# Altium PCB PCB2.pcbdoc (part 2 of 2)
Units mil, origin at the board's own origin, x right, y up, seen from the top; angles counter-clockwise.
Board outline 4920 x 2460 mil, 2 copper layers (Top Layer, Bottom Layer); 93 components, 68 nets, 331 pads, 95 vias.
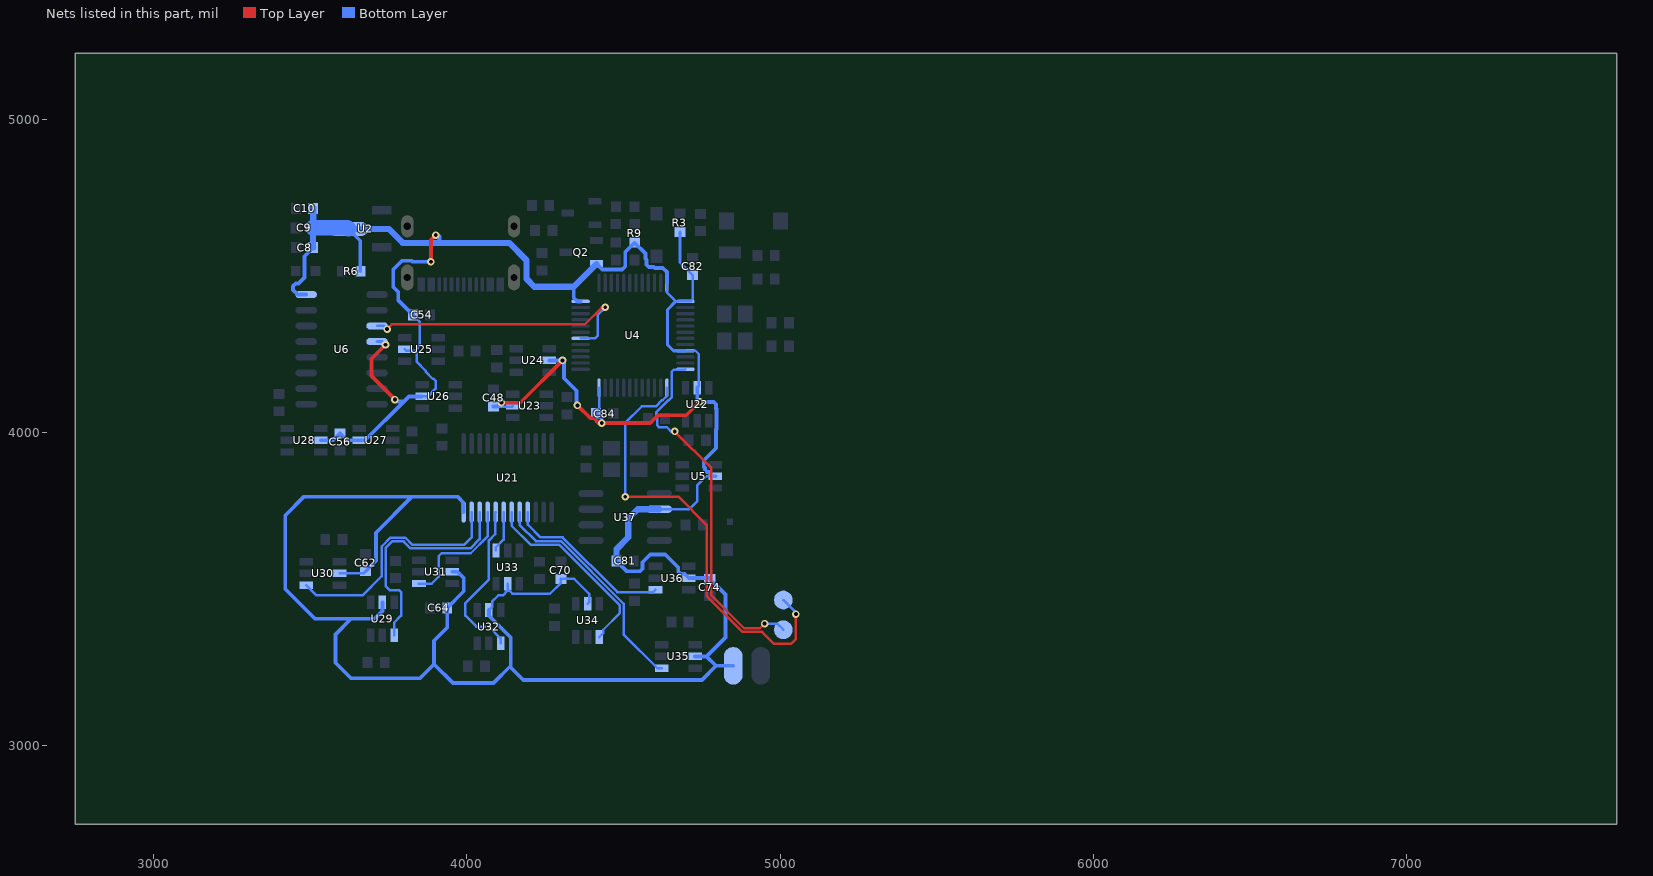
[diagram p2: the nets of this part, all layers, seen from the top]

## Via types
v1: diameter 24.02, hole 12.01, Top Layer to Bottom Layer, 95 vias

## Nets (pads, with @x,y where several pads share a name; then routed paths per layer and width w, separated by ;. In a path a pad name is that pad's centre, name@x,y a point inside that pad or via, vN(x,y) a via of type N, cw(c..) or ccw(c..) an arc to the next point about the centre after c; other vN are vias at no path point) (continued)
T9: U21.23 U30.1 | length 772.7
  Bottom Layer w8: U30.1@3486.85,3512.6 3519.45,3480 3666.87,3480 3727.98,3541.12 3727.98,3636.08 3755.91,3664.01 3802.98,3664.01 3824.98,3642.02 3992.02,3642.02 4015,3665 4015,3745.39 U21.23@4014.84,3745.55
T10: U21.22 U29.1 | length 743.4
  Bottom Layer w8: U29.1@3767.4,3351.85 3767.4,3392.4 3790,3415 3790,3490 3784.34,3495.66 3754.34,3495.66 3740,3510 3740,3631.1 3760.89,3651.99 3798.01,3651.99 3820,3630 4011.01,3630 4040.43,3659.42 U21.22@4040.43,3745.55
T11: U21.21 U31.1 | length 397.1
  Bottom Layer w8: U31.1@3846.85,3517.6 3887.6,3517.6 3910,3540 3910,3605 3919.2,3614.2 4012.2,3614.2 4066.02,3668.01 U21.21@4066.02,3745.55
T12: U21.20 U32.1 | length 528.7
  Bottom Layer w8: U21.20@4091.61,3745.55 4090,3743.94 4090,3675 4070,3655 4070,3530 3995,3455 3995,3415 4030,3380 4070,3380 4107.4,3342.6 U32.1@4107.4,3326.85
T13: U21.19 U33.1 | length 132.6
  Bottom Layer w8: U33.1@4092.6,3623.15 4092.6,3633.33 4117.2,3657.93 U21.19@4117.2,3745.55
T14: U21.18 U34.1 | length 622.2
  Bottom Layer w8: U21.18@4142.8,3745.55 4142.8,3702.2 4204.03,3640.97 4295.05,3640.97 4487.98,3448.03 4487.98,3422.98 4435,3370 4435,3359.45 U34.1@4422.4,3346.85
T15: U21.17 U35.1 | length 740.9
  Bottom Layer w8: U21.17@4168.39,3745.55 4168.39,3705 4220.41,3652.98 4300.02,3652.98 4500,3453.01 4500,3355 4607.4,3247.6 U35.1@4621.85,3247.6
T16: U21.16 U36.1 | length 540
  Bottom Layer w8: U21.16@4193.98,3745.55 4193.98,3706.02 4235,3665 4305,3665 4480,3490 4594.25,3490 U36.1@4601.85,3497.6
TX: U4.30 U6.3 | length 920.5
  Top Layer w8: v1(3745,4330) 3760,4345 4376.1,4345 4430.43,4399.33 v1(4441.75,4399.33)
  Bottom Layer w8: U6.3@3713.09,4340 3735,4340 v1(3745,4330) ; U4.30@4362.68,4300.16 4408.86,4300.16 4416.86,4308.16 4416.86,4374.43 v1(4441.75,4399.33)
USART2-RX: pad.1@5010,3465 U4.13 | length 1450.7
  Top Layer w8: v1(4505,3795) 4675,3795 4765,3705 4765,3478.01 4880.02,3362.98 4942.02,3362.98 4980,3325 5035,3325 5050,3340 v1(5050,3420)
  Bottom Layer w8: v1(4505,3795) 4505,4030 4557.98,4082.98 4602.98,4082.98 4623.17,4103.17 4624.92,4103.17 4638.27,4116.52 U4.13@4638.27,4142.68 ; pad.1@5010,3465 5050,3425 v1(5050,3420)
USART2-TX: pad.1@5010,3370 U4.12 | length 1164.8
  Top Layer w8: v1(4663.16,4003.16) 4780,3886.31 4780,3480 4885,3375 4935,3375 v1(4950,3390)
  Bottom Layer w8: v1(4663.16,4003.16) 4661.5,4001.5 4653.5,4001.5 4637.7,4017.3 4612.68,4017.3 4606.83,4023.15 4606.83,4048.17 4605,4050 4605,4065 4643.17,4103.17 4644.61,4103.17 4654.34,4112.9 4654.34,4194.34 4660,4200 4695.59,4200 U4.12@4697.32,4201.73 ; v1(4950,3390) 4990,3390 pad.1@5010,3370
VCC: C8.2 C9.2 C10.2 C48.1 C54.1 C56.1 C62.1 C64.1 C70.1 C74.1 C81.2 C82.2 C84.2 pad.1@4850,3255 Q2.2 R3.2 R6.1 R9.2 U2.2 U4.1 U4.9 U4.24 U4.36 U4.48 U5.5 U6.4 U6.16 U21.24 U22.5 U23.5 U24.5 U25.5 U26.5 U27.5 U28.5 U29.5 U30.5 U31.5 U32.5 U33.5 U34.5 U35.5 U36.5 U37.6 | length 11177.9
  Top Layer w12: v1(3740,4280) 3695,4235 3695,4180 v1(3770,4105) ; v1(3885,4545) 3885,4615 v1(3900,4630) ; v1(4110,4095) 4170,4095 v1(4305,4230) ; v1(4352.7,4086.35) 4394.05,4045 4405,4045 4420,4030 v1(4430,4030) 4585,4030 4610,4055 4700,4055 v1(4742.5,4097.5)
  Bottom Layer w8: U30.5@3593.15,3550 3669.76,3550 C62.1@3676.62,3556.86 ; U25.5@3801.85,4265 3806.19,4260.66 3834.34,4260.66 ; C54.1@3827.44,4375 3850,4352.44 3850,4281.99 3842.98,4274.98 3842.98,4269.3 3834.34,4260.66 ; U26.5@3856.85,4115 3875,4115 3900,4140 3900,4164.94 3893.95,4170.99 3890.91,4170.99 3867.97,4193.94 3867.97,4196.98 3840,4224.94 3840,4255 3834.34,4260.66 ; U32.5@4070,3433.15 4080,3443.15 4080,3460 4100,3480 4115,3480 4130,3495 U33.5@4130,3500 ; C48.1@4097.44,4082.44 4144.29,4082.44 U23.5@4146.85,4085 ; U33.5@4130,3516.85 U33.5@4130,3500 ; U34.5@4385,3453.15 4390,3458.15 4390,3485 4342.56,3532.44 C70.1@4300,3532.44 4300,3520 4265,3485 4145,3485 U33.5@4130,3500 ; C84.2@4412.44,4060 4421.73,4069.29 U4.24@4421.73,4142.68 ; U37.6@4614.15,3755 4710,3755 4735,3780 4735,3830 4765,3860 U5.5@4786.01,3860 ; U4.48@4638.27,4477.32 4638.27,4446.73 4666.73,4418.27 U4.1@4697.32,4418.27 4713.27,4418.27 4720,4425 C82.2@4720,4502.44 ; U4.9@4697.32,4260.79 4729.21,4260.79 4740,4250 4740,4148.15 U22.5@4735,4143.15
  Bottom Layer w10: U6.4@3713.09,4290 3730,4290 v1(3740,4280) ; 4666.73,4418.27 4640,4391.54 4640,4280 4659.21,4260.79 U4.9@4697.32,4260.79 ; R3.2@4680,4640.34 4680,4542.44 C82.2@4720,4502.44
  Bottom Layer w12: U6.16@3486.91,4440 3460,4440 3445,4455 3445,4467 3453.49,4475.49 3462.32,4475.49 3481.26,4494.42 3481.26,4562.36 C8.2@3509.11,4590.21 ; U28.5@3533.15,3975 3572.44,3975 C56.1@3595,3997.56 3617.56,3975 U27.5@3656.85,3975 3675,3975 3799.01,4099.01 ; U2.2@3621.61,4649.66 3659.66,4611.61 R6.1@3659.66,4515 ; C62.1@3676.62,3556.86 3710,3590.24 3710,3680 3825,3795 ; U29.5@3730,3458.15 3730,3430 3705,3405 3630,3405 ; v1(3770,4105) 3775.99,4099.01 3799.01,4099.01 ; C54.1@3827.44,4375 3781.01,4421.43 3781.01,4447.76 3765,4463.77 3765,4520 3792.95,4547.95 3823.04,4547.95 3825.99,4545 v1(3885,4545) ; U26.5@3856.85,4115 3815,4115 3799.01,4099.01 ; v1(3900,4630) 3907.89,4630 3913.47,4624.42 3913.47,4616.53 3901.94,4605 ; U31.5@3953.15,3555 3970,3555 3990,3535 3990,3492.84 C64.1@3936.95,3439.79 3936.95,3376.95 3895,3335 3895,3260 ; U21.24@3989.25,3745.55 3989.25,3775.75 3970,3795 3825,3795 ; U32.5@4070,3433.15 4070,3415 4140,3345 4140,3255 ; C48.1@4085,4082.44 4097.44,4082.44 v1(4110,4095) ; U24.5@4263.15,4230 v1(4305,4230) 4310,4225 4310,4172.97 4349.7,4133.27 4349.7,4089.35 v1(4352.7,4086.35) ; 4340.75,4465 4340.75,4430 4352.48,4418.27 U4.36@4362.68,4418.27 ; C84.2@4412.44,4060 4430,4042.44 v1(4430,4030) ; Q2.2@4413.74,4537.99 4431.74,4520 4494.9,4520 4505,4530.1 4505,4575.61 R9.2@4535.12,4605.73 4570,4570.85 4570,4555 4573.45,4551.55 4573.45,4535.47 4580.47,4528.45 4596.55,4528.45 4600,4525 4625,4525 4638.27,4511.73 U4.48@4638.27,4477.32 ; C81.2@4477.44,3590 4510.93,3556.51 4551.51,3556.51 4560,3565 4560,3567.03 4560.29,3567.32 4560.29,3585.29 4585,3610 4633.15,3610 4674.51,3568.64 4674.51,3555.62 4681.53,3548.6 4694.55,3548.6 U36.5@4708.15,3535 4772.56,3535 C74.1@4775,3532.56 4825,3482.56 4825,3345 4765,3285 ; U35.5@4728.15,3285 4765,3285 ; U22.5@4735,4143.15 4735,4105 v1(4742.5,4097.5) 4787.5,4097.5 4795,4090 4795,4076.33 4796.39,4074.94 4796.39,4010.43 4795,4009.04 4795,3949.66 4756.01,3910.67 4756.01,3890 4759.51,3886.5 4759.51,3880.62 4766.53,3873.6 4772.4,3873.6 4786.01,3860 U5.5@4793.15,3860 ; pad.1@4850,3255 4795,3255 ; 3630,3405 3580,3355 3580,3265 3630,3215 3850,3215 3895,3260 ; 3630,3405 3515,3405 3420,3500 3420,3735 3480,3795 3825,3795 ; 3895,3260 3955,3200 4085,3200 4140,3255 ; 4140,3255 4140,3250 4180,3210 4750,3210 4795,3255 ; 4765,3285 4795,3255
  Bottom Layer w20: C8.2@3509.11,4590.21 3508.17,4591.15 C9.2@3508.17,4653.08 3509.11,4654.02 C10.2@3509.11,4715.21 ; U2.2@3621.61,4649.66 3750.34,4649.66 3795,4605 3901.94,4605 4135,4605 4190,4550 4190,4490 4215,4465 4340.75,4465 Q2.2@4413.74,4537.99 ; C81.2@4477.44,3590 4477.44,3627.44 4515,3665 4515,3725 4545,3755 U37.6@4614.15,3755
  Bottom Layer w50: C9.2@3508.17,4653.08 3618.19,4653.08 U2.2@3621.61,4649.66
pads on no net: C4.1 C5.1 C6.1 C8.1 C9.1 C10.1 C12.1 C45.1 C47.1 C48.2 C49.1 C51.1 C53.1 C54.2 C55.1 C56.2 C57.1 C59.1 C61.1 C62.2 C63.1 C64.2 C65.1 C67.1 C69.1 C70.2 C71.1 C73.1 C74.2 C75.2 C76.1 C77.2 C78.2 C79.2 C80.2 C81.1 C82.1 C84.1 C85.1 SW5.1 U2.1 U4.2 U4.8 U4.10 U4.11 U4.16 U4.18 U4.19 U4.20 U4.21 U4.22 U4.23 U4.25 U4.26 U4.27 U4.28 U4.29 U4.34 U4.35 U4.37 U4.38 U4.45 U4.46 U4.47 U5.2 U5.4 U5.6 U6.1@3713.09,4440 U6.2@4830,3625 U6.7 U6.8 U6.9 U6.10 U6.11 U6.12 U6.15 U21.12 U21.15 U22.2 U22.4 U22.6 U23.2 U23.4 U23.6 U24.2 U24.4 U24.6 U25.2 U25.4 U25.6 U26.2 U26.4 U26.6 U27.2 U27.4 U27.6 U28.2 U28.4 U28.6 U29.2 U29.4 U29.6 U30.2 U30.4 U30.6 U31.2 U31.4 U31.6 U32.2 U32.4 U32.6 U33.2 U33.4 U33.6 U34.2 U34.4 U34.6 U35.2 U35.4 U35.6 U36.2 U36.4 U36.6 U37.8 U38.2 U38.4 U39.1 USB1.1 USB1.2 USB1.3 USB1.4 USB1.A1B12 USB1.A5 USB1.A8 USB1.B1A12 USB1.B5 USB1.B8 X1.2 X1.4
copper on no net: | length 4996.4
  Top Layer w8: v1(3695,4425) 3680,4440 3680,4615 3723.01,4658.01 3809.92,4658.01
  Bottom Layer w8: 3453.53,4515.14 3453.99,4515.6 3453.99,4590.21 ; 3486.85,3550 3515,3550 3530,3565 3530,3585.08 3602.58,3657.66 3630.93,3657.66 3676.62,3611.98 ; v1(3695,4425) 3698.09,4425 3713.09,4440 ; 3728.39,4709.06 3758.88,4709.06 3809.92,4658.01 ; 3763.15,3975 3797.44,3975 3825,4002.56 3865.42,4002.56 3893.17,3974.81 3902.63,3974.81 3920,3957.44 ; 3882.56,4375 3933.36,4324.2 3933.94,4324.2 3939.79,4318.35 3939.79,4317.77 3945,4312.56 3945,4300 3939.79,4294.79 3939.79,4286.45 3933.94,4280.6 3925.6,4280.6 3910,4265 3908.15,4265 ; 4057.58,3253.74 4070,3266.15 4070,3326.85 ; 4085,4137.56 4095,4147.56 4095,4207.44 4117.56,4230 4156.85,4230 4160,4230 4175.6,4214.4 4182.64,4214.4 4188.49,4208.55 4188.49,4201.51 4230,4160 4272.56,4160 4320,4112.56 4292.44,4085 4253.15,4085 ; 4150.08,4658.01 4150.08,4615.4 4208.02,4557.46 4208.02,4549.42 4240,4517.44 ; 4219.57,3745.55 4219.57,3725.43 4228.01,3716.99 4228.01,3711.95 4238.06,3701.9 4243.1,3701.9 4255,3690 4280,3690 4292.98,3702.98 4292.98,3905 4270.75,3927.23 4270.75,3964.45 ; 4231.36,3532.13 4286.79,3587.56 4300,3587.56 ; 4280,3437.56 4307.56,3410 4365,3410 4385,3390 4385,3346.85 ; v1(4380,4455) 4403.73,4431.27 ccw(c4425,4425.66) 4403.84,4419.67 4403.84,4411.67 4391.08,4398.92 ; v1@4390,4010 4418.9,4010 4420.89,4008.01 4439.11,4008.01 4454.76,4023.66 4454.76,4047.2 4467.56,4060 4441.42,4086.14 4441.42,4142.68 ; 4577.44,4045 4590,4032.44 4590,3979.44 4626.72,3942.72 4655,3914.44 4655,3891.85 4655.21,3891.64 4655.21,3881.45 4661.06,3875.6 4671.25,3875.6 4686.85,3860 4730,3860 4741.99,3871.99 4741.99,3954.43 4762.56,3975 4735,4002.56 4735,4036.85 ; 4697.32,4280.47 4729.53,4280.47 4770,4240 v1(4770,4215) ; 4720,4557.56 4745,4582.56 4745,4642.44 ; 5001.02,4675 4982.56,4656.54 4982.56,4565 4982.56,4490 5027.56,4445 5027.56,4350 5027.56,4275
  Bottom Layer w10: 3453.99,4590.21 3453.99,4652.14 3453.05,4653.08 3453.99,4654.02 3453.99,4715.21 3483.78,4745 3675,4745 3710.95,4709.06 3728.39,4709.06 ; 4532.56,3590 4532.56,3597.56 4590,3655 4614.15,3655
  Bottom Layer w12: 3809.92,4494.63 3831.37,4494.63 3854.01,4471.99 ; 4105.98,4471.99 4127.44,4471.99 4150.08,4494.63 ; 4240,4517.44 4247.44,4517.44 4275,4545 4275,4642.56 4272.56,4645 4262.56,4655 4262.56,4725
  Bottom Layer w20: 4614.15,3655 4659.1,3655 4690.88,3623.22 v1(4825.08,3623.22)
  other v1: 4100,3270 3465,3310 4215,3425 3595,3445 4905,3460 4655,3460.64 3826.1,3476.1 3540,3525.09 4105,3560 4025,3570 4327.94,3571.03 4705,3645 4315,3695 3905,3720 3540,3730 4460,3815 3755,3855 4379.89,3899.42 3480,3981.37 4540,4000 4390,4011.79 4491.76,4084.59 4015,4100 3602.07,4184.19 4585,4290 3410,4350 4980,4420 3560,4470 4680,4470 4295,4515 3567.59,4574.47 4605.12,4630.39 4040,4650 3905,4715

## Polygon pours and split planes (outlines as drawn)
no net on Bottom Layer (solid, remove dead copper, pour order 2): 3160,3000 5110,3000 5110,4960 3160,4960
no net on Top Layer (solid, remove dead copper): 3000,3120 5275,3120 5275,4875 3000,4875

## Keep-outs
Bottom Layer:
  region: 4564.9,3675.46 4811.77,3675.46 4811.77,3732.95 4564.9,3732.95
Board Outline Layer:
  lines w10: 3355,3273.43 ccw(c3453.43,3273.43) 3453.43,3175 4976.57,3175 ccw(c4976.57,3273.43) 5075,3273.43 5075,4671.57 ccw(c4976.57,4671.57) 4976.57,4770 3453.43,4770 ccw(c3453.43,4671.57) 3355,4671.57 3355,3273.43
Multi-Layer:
  region: 4811.77,3520 5072.99,3520 5072.99,4234.29 4811.77,4234.29
  region: 3940,4300 4330,4300 4330,4450 3940,4450

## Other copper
Top Layer:
  region net P8: 3548.31,4245 ccw(c3505,4245) 3461.69,4245 ccw(c3505,4245)
  region net P5: 3878.27,4245 ccw(c3834.96,4245) 3791.65,4245 ccw(c3834.96,4245)
  region net P4: 4193.23,4245 ccw(c4149.92,4245) 4106.61,4245 ccw(c4149.92,4245)
  region net P1: 4523.19,4245 ccw(c4479.88,4245) 4436.57,4245 ccw(c4479.88,4245)
  region net P7: 3703.35,3938.58 ccw(c3660.04,3938.58) 3616.73,3938.58 ccw(c3660.04,3938.58)
  region net P6: 4028.31,3943.58 ccw(c3985,3943.58) 3941.69,3943.58 ccw(c3985,3943.58)
  region net P3: 4353.27,3943.58 ccw(c4309.96,3943.58) 4266.65,3943.58 ccw(c4309.96,3943.58)
  region net P2: 4678.23,3938.58 ccw(c4634.92,3938.58) 4591.61,3938.58 ccw(c4634.92,3938.58)
  region net P16: 4523.19,3645 ccw(c4479.88,3645) 4436.57,3645 ccw(c4479.88,3645)
  region net P13: 4198.23,3640 ccw(c4154.92,3640) 4111.61,3640 ccw(c4154.92,3640)
  region net P11: 3873.27,3640 ccw(c3829.96,3640) 3786.65,3640 ccw(c3829.96,3640)
  region net P9: 3548.31,3645 ccw(c3505,3645) 3461.69,3645 ccw(c3505,3645)
  region net P10: 3703.35,3338.58 ccw(c3660.04,3338.58) 3616.73,3338.58 ccw(c3660.04,3338.58)
  region net P12: 4033.31,3338.58 ccw(c3990,3338.58) 3946.69,3338.58 ccw(c3990,3338.58)
  region net P14: 4348.27,3338.58 ccw(c4304.96,3338.58) 4261.65,3338.58 ccw(c4304.96,3338.58)
  region net P15: 4678.23,3338.58 ccw(c4634.92,3338.58) 4591.61,3338.58 ccw(c4634.92,3338.58)
  region: 3778.24,4654.01 3778.24,4662.01 3782.64,4662.1 3784.67,4662.33 3786.49,4662.76 3788.02,4663.47 3789.2,4664.54 3789.64,4665.23 3789.97,4666.03 3790.17,4666.95 3790.24,4668.01 3790.24,4648.01 3790.17,4649.07 3789.97,4649.99 3789.64,4650.79 3789.2,4651.48 3788.02,4652.55 3786.49,4653.26 3784.67,4653.69 3782.64,4653.92
  region net +5V: 3720,4560.59 3700,4560.59 3699.91,4563.24 3699.69,4565.74 3699,4570.12 3698.31,4573.34 3697.99,4575 3722.01,4575 3721.69,4573.34 3721,4570.12 3720.31,4565.74 3720.09,4563.24
  region net +5V: 4140.59,4710 4140.59,4730 4143.24,4730.09 4145.74,4730.31 4150.12,4731 4153.34,4731.69 4155,4732.01 4155,4707.99 4153.34,4708.31 4150.12,4709 4145.74,4709.69 4143.24,4709.91
  region net +5V: 3978.59,4569 3978.59,4581 3980.71,4581.22 3983.04,4581.84 3985.24,4582.77 3986.99,4583.95 3986.99,4566.05 3985.24,4567.23 3983.04,4568.16 3980.71,4568.78
  region net NRST: 4747.17,4297.17 4752.83,4302.83 4753.77,4302.05 4754.64,4301.62 4755.49,4301.46 4756.34,4301.5 4758.25,4301.84 4759.37,4301.98 4760.67,4301.99 4748.01,4289.33 4748.02,4290.63 4748.16,4291.75 4748.5,4293.66 4748.54,4294.51 4748.38,4295.36 4747.95,4296.23
  region net NRST: 4644,4538.59 4636,4538.59 4635.89,4539.9 4635.57,4541.08 4635.09,4542.15 4634.45,4543.15 4632.87,4545.04 4631.05,4546.99 4648.95,4546.99 4647.13,4545.04 4645.55,4543.15 4644.91,4542.15 4644.43,4541.08 4644.11,4539.9
  region net VCC: 3732.64,4264.15 3724.15,4272.64 3725.5,4274.3 3726.71,4276.37 3727.6,4278.59 3728.01,4280.67 3740.67,4268.01 3738.59,4267.6 3736.37,4266.71 3734.3,4265.5
  region net P2: 4703.59,3911 4703.59,3919 4704.9,3919.11 4706.08,3919.43 4707.15,3919.91 4708.15,3920.55 4710.04,3922.13 4711.99,3923.95 4711.99,3906.05 4710.04,3907.87 4708.15,3909.45 4707.15,3910.09 4706.08,3910.57 4704.9,3910.89
  region net P1: 4670.57,4088.78 4676.22,4094.43 4677.23,4093.58 4678.29,4092.97 4679.39,4092.56 4680.54,4092.3 4683,4092.09 4685.67,4091.99 4673.01,4079.33 4672.91,4082 4672.7,4084.46 4672.44,4085.61 4672.03,4086.71 4671.42,4087.77
  region net T1: 4763.62,4050.57 4757.97,4056.22 4758.82,4057.23 4759.43,4058.29 4759.84,4059.39 4760.1,4060.54 4760.31,4063 4760.41,4065.67 4773.07,4053.01 4770.4,4052.91 4767.94,4052.7 4766.79,4052.44 4765.69,4052.03 4764.63,4051.42
  region net T1: 4199,3903.59 4191,3903.59 4190.89,3904.9 4190.57,3906.08 4190.09,3907.15 4189.45,3908.15 4187.87,3910.04 4186.05,3911.99 4203.95,3911.99 4202.13,3910.04 4200.55,3908.15 4199.91,3907.15 4199.43,3906.08 4199.11,3904.9
  region net T2: 4696.22,3833.12 4701.88,3838.78 4702.89,3837.93 4703.94,3837.32 4705.05,3836.9 4706.2,3836.65 4708.65,3836.43 4711.32,3836.33 4698.67,3823.68 4698.57,3826.35 4698.35,3828.8 4698.1,3829.95 4697.68,3831.06 4697.07,3832.11
  region net P4: 4193.59,4251 4193.59,4259 4194.9,4259.11 4196.08,4259.43 4197.15,4259.91 4198.15,4260.55 4200.04,4262.13 4201.99,4263.95 4201.99,4246.05 4200.04,4247.87 4198.15,4249.45 4197.15,4250.09 4196.08,4250.57 4194.9,4250.89
  region net P3: 4309.43,4026.22 4303.78,4020.57 4302.77,4021.42 4301.71,4022.03 4300.61,4022.44 4299.46,4022.7 4297,4022.91 4294.33,4023.01 4306.99,4035.67 4307.09,4033 4307.3,4030.54 4307.56,4029.39 4307.97,4028.29 4308.58,4027.23
  region net P5: 3890.57,4213.78 3896.22,4219.43 3897.23,4218.58 3898.29,4217.97 3899.39,4217.56 3900.54,4217.3 3903,4217.09 3905.67,4216.99 3893.01,4204.33 3892.91,4207 3892.7,4209.46 3892.44,4210.61 3892.03,4211.71 3891.42,4212.77
  region net P6: 3964,4028.59 3956,4028.59 3955.89,4029.9 3955.57,4031.08 3955.09,4032.15 3954.45,4033.15 3952.87,4035.04 3951.05,4036.99 3968.95,4036.99 3967.13,4035.04 3965.55,4033.15 3964.91,4032.15 3964.43,4031.08 3964.11,4029.9
  region net P8: 3416,4096.41 3424,4096.41 3424.11,4095.1 3424.43,4093.92 3424.91,4092.85 3425.55,4091.85 3427.13,4089.96 3428.95,4088.01 3411.05,4088.01 3412.87,4089.96 3414.45,4091.85 3415.09,4092.85 3415.57,4093.92 3415.89,4095.1
  region net P7: 3718.59,3921 3718.59,3929 3719.9,3929.11 3721.08,3929.43 3722.15,3929.91 3723.15,3930.55 3725.04,3932.13 3726.99,3933.95 3726.99,3916.05 3725.04,3917.87 3723.15,3919.45 3722.15,3920.09 3721.08,3920.57 3719.9,3920.89
  region net P16: 4496,3539.41 4504,3533.41 4504.21,3530.66 4504.77,3528.41 4506.47,3523.55 4490.2,3531.01 4491.28,3531.6 4492.33,3532.41 4493.31,3533.39 4494.19,3534.5 4494.93,3535.69 4495.5,3536.94 4495.87,3538.19
  region net P15: 4597.14,3373.52 4588.12,3371.23 4582.84,3376.12 4577.34,3380.76 4594.81,3383.08 4594.18,3381.9 4593.89,3380.66 4593.9,3379.41 4594.17,3378.14 4594.66,3376.9 4595.35,3375.7
  region net P13: 4176,3586.41 4184,3586.41 4184.11,3585.1 4184.43,3583.92 4184.91,3582.85 4185.55,3581.85 4187.13,3579.96 4188.95,3578.01 4171.05,3578.01 4172.87,3579.96 4174.45,3581.85 4175.09,3582.85 4175.57,3583.92 4175.89,3585.1
  region net P14: 4346.22,3365.57 4340.57,3371.22 4341.42,3372.23 4342.03,3373.29 4342.44,3374.39 4342.7,3375.54 4342.91,3378 4343.01,3380.67 4355.67,3368.01 4353,3367.91 4350.54,3367.7 4349.39,3367.44 4348.29,3367.03 4347.23,3366.42
  region net P12: 3983.78,3244.43 3989.43,3238.78 3988.58,3237.77 3987.97,3236.71 3987.56,3235.61 3987.3,3234.46 3987.09,3232 3986.99,3229.33 3974.33,3241.99 3977,3242.09 3979.46,3242.3 3980.61,3242.56 3981.71,3242.97 3982.77,3243.58
  region net P11: 3786.41,3634 3786.41,3626 3785.1,3625.89 3783.92,3625.57 3782.85,3625.09 3781.85,3624.45 3779.96,3622.87 3778.01,3621.05 3778.01,3638.95 3779.96,3637.13 3781.85,3635.55 3782.85,3634.91 3783.92,3634.43 3785.1,3634.11
  region net P9: 3464.43,3691.22 3458.78,3685.57 3457.77,3686.42 3456.71,3687.03 3455.61,3687.44 3454.46,3687.7 3452,3687.91 3449.33,3688.01 3461.99,3700.67 3462.09,3698 3462.3,3695.54 3462.56,3694.39 3462.97,3693.29 3463.58,3692.23
  region net P10: 3652.17,3262.83 3657.83,3257.17 3657.05,3256.23 3656.62,3255.36 3656.46,3254.51 3656.5,3253.66 3656.84,3251.75 3656.98,3250.63 3656.99,3249.33 3644.33,3261.99 3645.63,3261.98 3646.75,3261.84 3648.66,3261.5 3649.51,3261.46 3650.36,3261.62 3651.23,3262.05
  region net $R7_1: 4561.22,4720.57 4555.57,4726.22 4556.42,4727.23 4557.03,4728.29 4557.44,4729.39 4557.7,4730.54 4557.91,4733 4558.01,4735.67 4570.67,4723.01 4568,4722.91 4565.54,4722.7 4564.39,4722.44 4563.29,4722.03 4562.23,4721.42
  region net $Q1_2: 3586.41,4424 3586.41,4416 3585.1,4415.89 3583.92,4415.57 3582.85,4415.09 3581.85,4414.45 3579.96,4412.87 3578.01,4411.05 3578.01,4428.95 3579.96,4427.13 3581.85,4425.55 3582.85,4424.91 3583.92,4424.43 3585.1,4424.11
  region net $R7_1: 3634.92,4395.49 3634.92,4387.49 3633.61,4387.38 3632.43,4387.07 3631.36,4386.58 3630.36,4385.95 3628.47,4384.36 3626.51,4382.54 3626.51,4400.44 3628.47,4398.62 3630.36,4397.04 3631.36,4396.41 3632.43,4395.92 3633.61,4395.6
  region net RX: 3759.43,4366.22 3753.78,4360.57 3752.77,4361.42 3751.71,4362.03 3750.61,4362.44 3749.46,4362.7 3747,4362.91 3744.33,4363.01 3756.99,4375.67 3757.09,4373 3757.3,4370.54 3757.56,4369.39 3757.97,4368.29 3758.58,4367.23
  region net TX: 4424.52,4387.76 4421.66,4396.21 4433.32,4407.88 4434.06,4390.11 4432.89,4390.85 4431.67,4391.21 4430.44,4391.23 4429.2,4390.94 4427.97,4390.41 4426.77,4389.67
  region net USART2-RX: 4521.41,3799 4521.41,3791 4520.1,3790.89 4518.92,3790.57 4517.85,3790.09 4516.85,3789.45 4514.96,3787.87 4513.01,3786.05 4513.01,3803.95 4514.96,3802.13 4516.85,3800.55 4517.85,3799.91 4518.92,3799.43 4520.1,3799.11
  region net USART2-TX: 4677.59,3994.38 4671.93,3988.72 4670.93,3989.57 4669.87,3990.18 4668.77,3990.6 4667.62,3990.85 4665.16,3991.07 4662.49,3991.17 4675.15,4003.82 4675.25,4001.15 4675.46,3998.7 4675.72,3997.55 4676.13,3996.44 4676.74,3995.39
  region net O: 4031.41,4024 4031.41,4016 4030.1,4015.89 4028.92,4015.57 4027.85,4015.09 4026.85,4014.45 4024.96,4012.87 4023.01,4011.05 4023.01,4028.95 4024.96,4027.13 4026.85,4025.55 4027.85,4024.91 4028.92,4024.43 4030.1,4024.11
  region net A: 4469.43,4421.22 4463.78,4415.57 4462.77,4416.42 4461.71,4417.03 4460.61,4417.44 4459.46,4417.7 4457,4417.91 4454.33,4418.01 4466.99,4430.67 4467.09,4428 4467.3,4425.54 4467.56,4424.39 4467.97,4423.29 4468.58,4422.23
  region net C: 4524,4394.5 4516,4394.5 4515.89,4395.78 4515.57,4396.85 4515.09,4397.78 4514.45,4398.6 4512.87,4400.18 4511.05,4401.99 4528.95,4401.99 4527.13,4400.18 4525.55,4398.6 4524.91,4397.78 4524.43,4396.85 4524.11,4395.78
  region net D: 4559,4368.59 4551,4368.59 4550.89,4369.9 4550.57,4371.08 4550.09,4372.15 4549.45,4373.15 4547.87,4375.04 4546.05,4376.99 4563.95,4376.99 4562.13,4375.04 4560.55,4373.15 4559.91,4372.15 4559.43,4371.08 4559.11,4369.9
  region net USART2-RX: 5054,3403.59 5046,3403.59 5045.89,3404.9 5045.57,3406.08 5045.09,3407.15 5044.45,3408.15 5042.87,3410.04 5041.05,3411.99 5058.95,3411.99 5057.13,3410.04 5055.55,3408.15 5054.91,3407.15 5054.43,3406.08 5054.11,3404.9
  region net VCC: 3754.15,4112.36 3762.64,4120.85 3764.3,4119.5 3766.37,4118.29 3768.59,4117.4 3770.67,4116.99 3758.01,4104.33 3757.6,4106.41 3756.71,4108.63 3755.5,4110.7
  region net VCC: 3879,4561.41 3891,4561.41 3891.22,4559.29 3891.84,4556.96 3892.77,4554.76 3893.95,4553.01 3876.05,4553.01 3877.23,4554.76 3878.16,4556.96 3878.78,4559.29
  region net VCC: 3892.64,4614.15 3884.15,4622.64 3885.5,4624.3 3886.71,4626.37 3887.6,4628.59 3888.01,4630.67 3900.67,4618.01 3898.59,4617.6 3896.37,4616.71 3894.3,4615.5
  region net VCC: 4409.81,4031.7 4414.92,4043.56 4416.91,4041.47 4418.81,4039.75 4419.77,4039.22 4420.78,4038.99 4421.85,4039.15 4423.01,4039.76 4420.76,4022.34 4419.27,4024 4417.93,4025.28 4415.45,4027.17 4412.9,4028.99 4411.45,4030.17
  region net VCC: 4446.41,4036 4446.41,4024 4444.29,4023.78 4441.96,4023.16 4439.76,4022.23 4438.01,4021.05 4438.01,4038.95 4439.76,4037.77 4441.96,4036.84 4444.29,4036.22
  region net VCC: 4368.55,4078.99 4360.06,4070.51 4358.4,4071.85 4356.33,4073.06 4354.11,4073.95 4352.03,4074.36 4364.69,4087.02 4365.1,4084.94 4365.99,4082.73 4367.2,4080.65
  region net VCC: 4126.41,4101 4126.41,4089 4124.29,4088.78 4121.96,4088.16 4119.76,4087.23 4118.01,4086.05 4118.01,4103.95 4119.76,4102.77 4121.96,4101.84 4124.29,4101.22
  region net VCC: 4297.64,4214.15 4289.15,4222.64 4290.5,4224.3 4291.71,4226.37 4292.6,4228.59 4293.01,4230.67 4305.67,4218.01 4303.59,4217.6 4301.37,4216.71 4299.3,4215.5
  region net VCC: 4735.14,4081.65 4726.65,4090.14 4728,4091.8 4729.21,4093.87 4730.1,4096.09 4730.51,4098.17 4743.17,4085.51 4741.09,4085.1 4738.87,4084.21 4736.8,4083
  region net +5V: 3972.31,4570.76 ccw(c3987.72,4554.07) 3965,4554.07 3955,4596.55 3965,4620.55 ccw(c4026.92,4620.55) 3980.79,4579.24
Bottom Layer:
  drawing of 322 lines, arcs and shapes, not listed

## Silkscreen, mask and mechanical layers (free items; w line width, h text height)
Bottom Silkscreen Layer:
  region: 3825,4380 4135,4380 4135,4450 3825,4450
  text "12pf" at 5065,4115 h98.43
  text "2.7pf" at 5060,4015 h98.43
  text "100nf" at 5065,3915 h98.43
  text "10uf /  10KR" at 5065,3720 h98.43
  text "cyihnltxy  /  16键位测试板" at 3865,3710 h78.74
  text "120pf" at 5065,3635 h98.43
  text "1KR" at 5060,3545 h98.43
Mech6:
  region: 3657.8,4230 ccw(c3520,4230) 3382.2,4230 ccw(c3520,4230)
  region: 3812.83,3938.58 ccw(c3675.04,3938.58) 3537.24,3938.58 ccw(c3675.04,3938.58)
  region: 3972.76,4230 ccw(c3834.96,4229.2) 3697.17,4230 ccw(c3834.96,4230.8)
  region: 4127.8,3938.58 ccw(c3990,3938.58) 3852.2,3938.58 ccw(c3990,3938.58)
  region: 4287.72,4230 ccw(c4149.92,4229.26) 4012.13,4230 ccw(c4149.92,4230.74)
  region: 4442.76,3938.58 ccw(c4304.96,3937.79) 4167.17,3938.58 ccw(c4304.96,3939.38)
  region: 4602.68,4230 ccw(c4464.88,4229.32) 4327.09,4230 ccw(c4464.88,4230.68)
  region: 4757.72,3938.58 ccw(c4619.92,3937.84) 4482.13,3938.58 ccw(c4619.92,3939.32)
  region: 3657.8,3645 ccw(c3520,3645) 3382.2,3645 ccw(c3520,3645)
  region: 3812.83,3353.58 ccw(c3675.04,3353.58) 3537.24,3353.58 ccw(c3675.04,3353.58)
  region: 3972.76,3645 ccw(c3834.96,3644.2) 3697.17,3645 ccw(c3834.96,3645.8)
  region: 4127.8,3353.58 ccw(c3990,3353.58) 3852.2,3353.58 ccw(c3990,3353.58)
  region: 4287.72,3645 ccw(c4149.92,3644.26) 4012.13,3645 ccw(c4149.92,3645.74)
  region: 4442.76,3353.58 ccw(c4304.96,3352.79) 4167.17,3353.58 ccw(c4304.96,3354.38)
  region: 4602.68,3645 ccw(c4464.88,3644.32) 4327.09,3645 ccw(c4464.88,3645.68)
  region: 4757.72,3353.58 ccw(c4619.92,3352.84) 4482.13,3353.58 ccw(c4619.92,3354.32)
  text "这个天线真的没办法 做成填充DRC过不去 /  反正下单的时候自己改成底层吧qwq" at 5140,3715 h120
